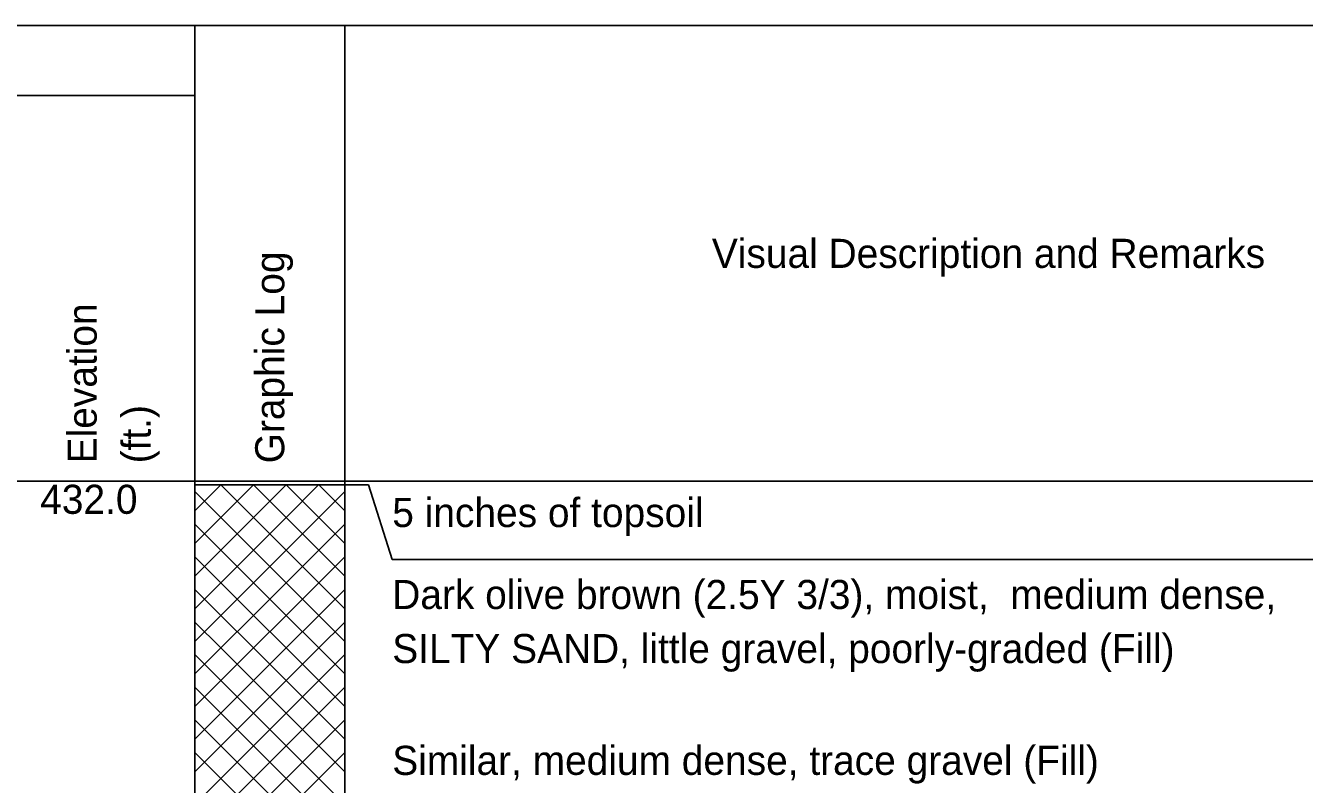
# Model space of a CAD drawing. Extents: x 9419 to 9552, y 6780 to 6865.
# Drawn here: x 9437.02 to 9446.82, y 6844.71 to 6850.53 of the extents above; entities that cross this region are included whole.
import ezdxf

# ---------------------------------------------------------------- set-up
doc = ezdxf.new("R2010")
doc.units = 0
doc.layers.add('7', color=7, linetype='Continuous')
doc.layers.add('8', color=7, linetype='Continuous')

msp = doc.modelspace()

# ---------------------------------------------------------------- linework, layer by layer
at = {"layer": '7'}
for p, q in [((9438.3144, 6847.0106), (9438.3144, 6847.0096)), ((9439.4627, 6847.0106), (9438.3144, 6847.0106)), ((9438.3144, 6847.0096), (9439.4627, 6847.0096)), ((9438.3144, 6847.0096), (9438.3144, 6843.0106)), ((9439.4627, 6847.0096), (9438.3144, 6847.0096)), ((9439.4627, 6847.0096), (9439.4627, 6847.0106)), ((9439.4627, 6843.0106), (9439.4627, 6847.0096)), ((9439.4627, 6847.0096), (9439.645, 6847.0096)), ((9439.645, 6847.0096), (9439.8273, 6846.4384)), ((9439.8273, 6846.4384), (9450.2505, 6846.4384))]:
    msp.add_line(p, q, dxfattribs=at)
for points in [[(9422.4492, 6850.5283), (9453.9452, 6850.5283)], [(9438.3144, 6850.5283), (9438.3144, 6821.9829)], [(9439.4627, 6850.5283), (9439.4627, 6821.9829)], [(9423.5669, 6849.9919), (9438.3144, 6849.9919)], [(9422.4492, 6847.0384), (9453.9452, 6847.0384)]]:
    msp.add_lwpolyline(points, dxfattribs=at)
at = {"layer": '8'}
for p, q in [((9438.3144, 6846.811), (9438.5131, 6847.0096)), ((9438.3472, 6847.0106), (9438.3467, 6847.0096)), ((9438.4719, 6847.0101), (9438.4724, 6847.0096)), ((9438.5136, 6846.7601), (9438.7631, 6847.0096)), ((9438.7636, 6846.7601), (9438.5141, 6847.0096)), ((9438.5347, 6847.0106), (9438.5342, 6847.0096)), ((9438.6594, 6847.0101), (9438.6599, 6847.0096)), ((9438.7222, 6847.0106), (9438.7217, 6847.0096)), ((9438.7636, 6846.7601), (9439.0131, 6847.0096)), ((9439.0136, 6846.7601), (9438.7641, 6847.0096)), ((9438.8469, 6847.0101), (9438.8474, 6847.0096)), ((9438.9097, 6847.0106), (9438.9092, 6847.0096)), ((9439.0136, 6846.7601), (9439.2631, 6847.0096)), ((9439.2636, 6846.7601), (9439.0141, 6847.0096)), ((9439.0344, 6847.0101), (9439.0349, 6847.0096)), ((9439.0972, 6847.0106), (9439.0967, 6847.0096)), ((9439.2219, 6847.0101), (9439.2224, 6847.0096)), ((9439.4627, 6846.811), (9439.2641, 6847.0096)), ((9439.2847, 6847.0106), (9439.2842, 6847.0096)), ((9439.4094, 6847.0101), (9439.4099, 6847.0096)), ((9438.5136, 6846.7601), (9438.3144, 6846.9592)), ((9439.2636, 6846.7601), (9439.4627, 6846.9592)), ((9438.3144, 6846.561), (9438.5136, 6846.7601)), ((9438.5136, 6846.5101), (9438.3144, 6846.7092)), ((9438.7636, 6846.5101), (9438.5136, 6846.7601)), ((9438.5136, 6846.5101), (9438.7636, 6846.7601)), ((9439.0136, 6846.5101), (9438.7636, 6846.7601)), ((9438.7636, 6846.5101), (9439.0136, 6846.7601)), ((9439.2636, 6846.5101), (9439.0136, 6846.7601)), ((9439.0136, 6846.5101), (9439.2636, 6846.7601)), ((9439.4627, 6846.561), (9439.2636, 6846.7601)), ((9439.2636, 6846.5101), (9439.4627, 6846.7092)), ((9438.3144, 6846.311), (9438.5136, 6846.5101)), ((9438.7636, 6846.2601), (9438.5136, 6846.5101)), ((9438.5136, 6846.2601), (9438.7636, 6846.5101)), ((9439.0136, 6846.2601), (9438.7636, 6846.5101)), ((9438.7636, 6846.2601), (9439.0136, 6846.5101)), ((9439.2636, 6846.2601), (9439.0136, 6846.5101)), ((9439.0136, 6846.2601), (9439.2636, 6846.5101)), ((9439.4627, 6846.311), (9439.2636, 6846.5101)), ((9438.5136, 6846.2601), (9438.3144, 6846.4592)), ((9439.2636, 6846.2601), (9439.4627, 6846.4592)), ((9438.3144, 6846.061), (9438.5136, 6846.2601)), ((9438.5136, 6846.0101), (9438.3144, 6846.2092)), ((9438.7636, 6846.0101), (9438.5136, 6846.2601)), ((9438.5136, 6846.0101), (9438.7636, 6846.2601)), ((9439.0136, 6846.0101), (9438.7636, 6846.2601)), ((9438.7636, 6846.0101), (9439.0136, 6846.2601)), ((9439.2636, 6846.0101), (9439.0136, 6846.2601)), ((9439.0136, 6846.0101), (9439.2636, 6846.2601)), ((9439.4627, 6846.061), (9439.2636, 6846.2601)), ((9439.2636, 6846.0101), (9439.4627, 6846.2092)), ((9438.3144, 6845.811), (9438.5136, 6846.0101)), ((9438.7636, 6845.7601), (9438.5136, 6846.0101)), ((9438.5136, 6845.7601), (9438.7636, 6846.0101)), ((9439.0136, 6845.7601), (9438.7636, 6846.0101)), ((9438.7636, 6845.7601), (9439.0136, 6846.0101)), ((9439.2636, 6845.7601), (9439.0136, 6846.0101)), ((9439.0136, 6845.7601), (9439.2636, 6846.0101)), ((9439.4627, 6845.811), (9439.2636, 6846.0101)), ((9438.5136, 6845.7601), (9438.3144, 6845.9592)), ((9439.2636, 6845.7601), (9439.4627, 6845.9592)), ((9438.3144, 6845.561), (9438.5136, 6845.7601)), ((9438.5136, 6845.5101), (9438.3144, 6845.7092)), ((9438.7636, 6845.5101), (9438.5136, 6845.7601)), ((9438.5136, 6845.5101), (9438.7636, 6845.7601)), ((9439.0136, 6845.5101), (9438.7636, 6845.7601)), ((9438.7636, 6845.5101), (9439.0136, 6845.7601)), ((9439.2636, 6845.5101), (9439.0136, 6845.7601)), ((9439.0136, 6845.5101), (9439.2636, 6845.7601)), ((9439.4627, 6845.561), (9439.2636, 6845.7601)), ((9439.2636, 6845.5101), (9439.4627, 6845.7092)), ((9438.3144, 6845.311), (9438.5136, 6845.5101)), ((9438.7636, 6845.2601), (9438.5136, 6845.5101)), ((9438.5136, 6845.2601), (9438.7636, 6845.5101)), ((9439.0136, 6845.2601), (9438.7636, 6845.5101)), ((9438.7636, 6845.2601), (9439.0136, 6845.5101)), ((9439.2636, 6845.2601), (9439.0136, 6845.5101)), ((9439.0136, 6845.2601), (9439.2636, 6845.5101)), ((9439.4627, 6845.311), (9439.2636, 6845.5101)), ((9438.5136, 6845.2601), (9438.3144, 6845.4592)), ((9439.2636, 6845.2601), (9439.4627, 6845.4592)), ((9438.3144, 6845.061), (9438.5136, 6845.2601)), ((9438.5136, 6845.0101), (9438.3144, 6845.2092)), ((9438.7636, 6845.0101), (9438.5136, 6845.2601)), ((9438.5136, 6845.0101), (9438.7636, 6845.2601)), ((9439.0136, 6845.0101), (9438.7636, 6845.2601)), ((9438.7636, 6845.0101), (9439.0136, 6845.2601)), ((9439.2636, 6845.0101), (9439.0136, 6845.2601)), ((9439.0136, 6845.0101), (9439.2636, 6845.2601)), ((9439.4627, 6845.061), (9439.2636, 6845.2601)), ((9439.2636, 6845.0101), (9439.4627, 6845.2092)), ((9438.3144, 6844.811), (9438.5136, 6845.0101)), ((9438.7636, 6844.7601), (9438.5136, 6845.0101)), ((9438.5136, 6844.7601), (9438.7636, 6845.0101)), ((9439.0136, 6844.7601), (9438.7636, 6845.0101)), ((9438.7636, 6844.7601), (9439.0136, 6845.0101)), ((9439.2636, 6844.7601), (9439.0136, 6845.0101)), ((9439.0136, 6844.7601), (9439.2636, 6845.0101)), ((9439.4627, 6844.811), (9439.2636, 6845.0101)), ((9438.5136, 6844.7601), (9438.3144, 6844.9593)), ((9439.2636, 6844.7601), (9439.4627, 6844.9593)), ((9438.3144, 6844.561), (9438.5136, 6844.7601)), ((9438.7636, 6844.5101), (9438.5136, 6844.7601)), ((9438.5136, 6844.5101), (9438.7636, 6844.7601)), ((9439.0136, 6844.5101), (9438.7636, 6844.7601)), ((9438.7636, 6844.5101), (9439.0136, 6844.7601)), ((9439.2636, 6844.5101), (9439.0136, 6844.7601)), ((9439.0136, 6844.5101), (9439.2636, 6844.7601)), ((9439.4627, 6844.561), (9439.2636, 6844.7601))]:
    msp.add_line(p, q, dxfattribs=at)

# ---------------------------------------------------------------- texts
at = {"layer": '7'}
for s, height, p in [('Visual Description and Remarks', 0.222801, (9442.2762, 6848.6719)), ('432.0', 0.2228, (9437.1297, 6846.7878)), ('5 inches of topsoil', 0.2228, (9439.8273, 6846.6865)), ('Dark olive brown (2.5Y 3/3), moist,  medium dense,', 0.2228, (9439.8273, 6846.0586)), ('SILTY SAND, little gravel, poorly-graded (Fill)', 0.2228, (9439.8273, 6845.6444)), ('Similar, medium dense, trace gravel (Fill)', 0.2228, (9439.8273, 6844.7878))]:
    msp.add_text(s, height=height, dxfattribs=at).set_placement(p)
for s, height, p in [('Graphic Log', 0.222801, (9439, 6847.1747)), ('Elevation', 0.2228, (9437.5626, 6847.1747)), ('(ft.)', 0.2228, (9437.9768, 6847.1747))]:
    msp.add_text(s, height=height, rotation=90, dxfattribs=at).set_placement(p)

doc.saveas('drawing.dxf')
